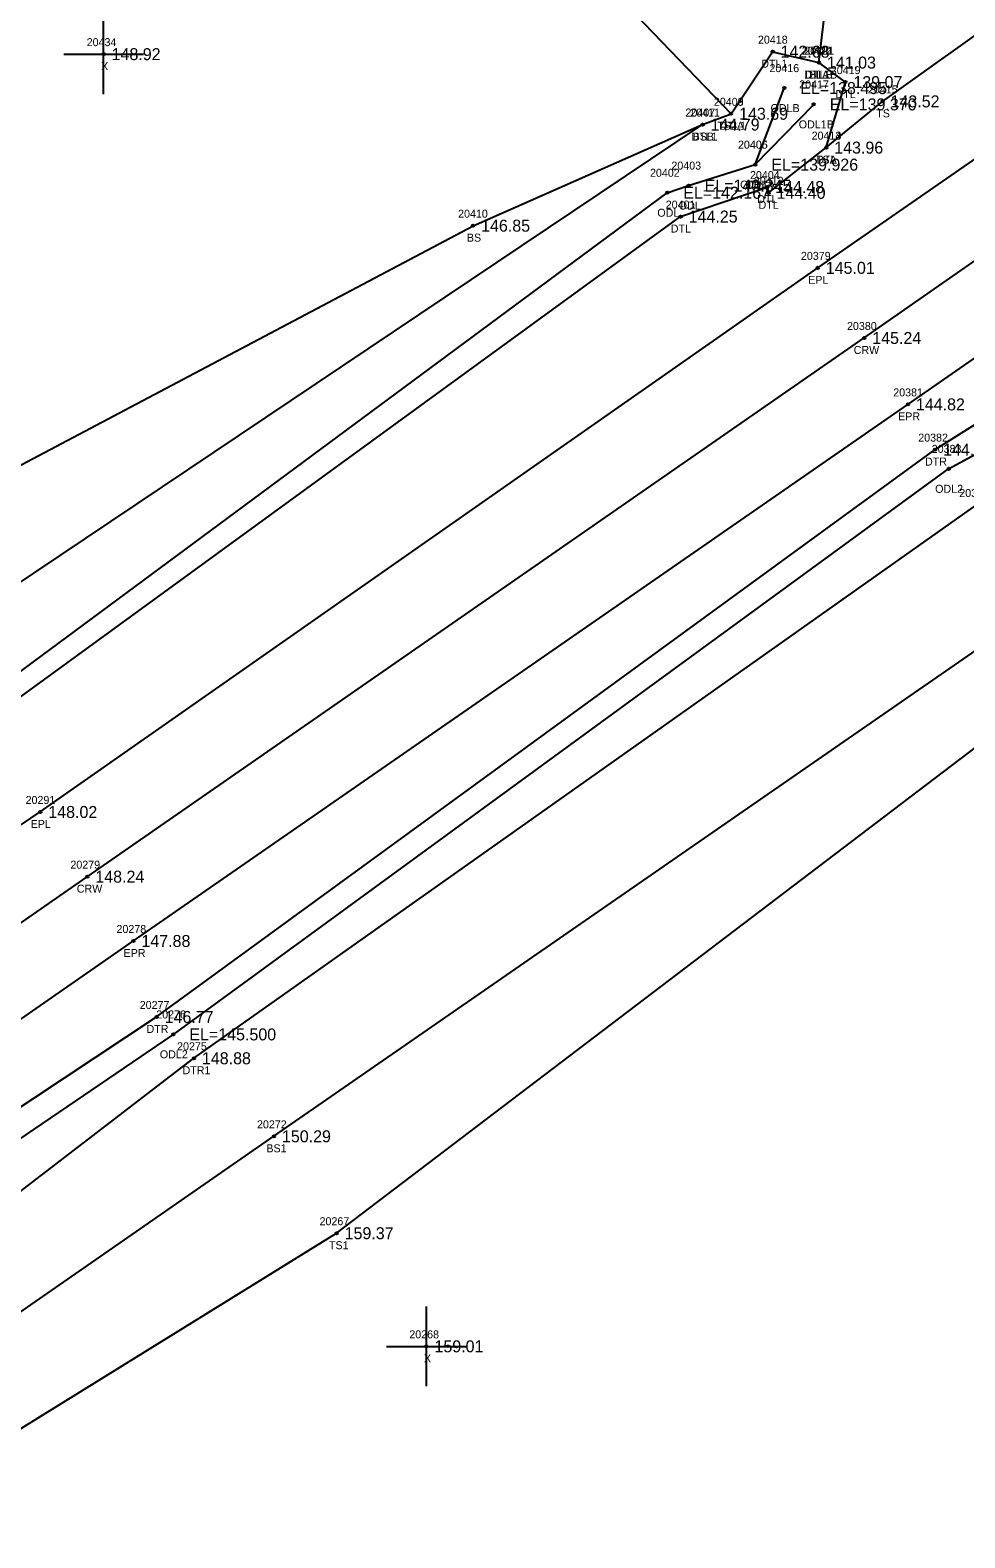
# Model space of a CAD drawing. Extents: x 2449605 to 2452431, y 1012876 to 1014922.
# Drawn here: x 2450635.2 to 2450752.2, y 1013571.4 to 1013760.1 of the extents above; entities that cross this region are included whole.
import ezdxf

# ---------------------------------------------------------------- set-up
doc = ezdxf.new("R2010")
doc.units = 0
for name, color, linetype in [('RD_DTM_BkLn1', 7, 'Continuous'), ('RD_DTM_BkLn2', 7, 'Continuous'), ('RD_DTM_BkLn_txCode', 7, 'Continuous'), ('RD_EX_H2O', 7, 'Continuous'), ('RD_EX_H2O_txCode', 7, 'Continuous'), ('RD_EX_Misc', 7, 'Continuous'), ('RD_EX_Misc_txCode', 7, 'Continuous'), ('RD_EX_Road', 7, 'Continuous'), ('RD_EX_Road_txCode', 7, 'Continuous'), ('RD_EX_TX_H2O_ELEV', 7, 'Continuous'), ('RD_EX_TX_Misc_ELEV', 7, 'Continuous'), ('RD_EX_TX_Road_ELEV', 7, 'Continuous'), ('RD_HC_Survey_ELEV', 7, 'Continuous'), ('RD_HC_Survey_txCode', 7, 'Continuous'), ('RD_SMD_Locator', 7, 'Continuous')]:
    doc.layers.add(name, color=color, linetype=linetype)

msp = doc.modelspace()

# ---------------------------------------------------------------- linework, layer by layer
at = {"layer": 'RD_DTM_BkLn1'}
msp.add_line((2450733.94, 1013756.08), (2450735.55, 1013769.66), dxfattribs=at)
msp.add_lwpolyline([(2449680.58, 1012985.87), (2449759.39, 1013040.31), (2449841.07, 1013097.15), (2449921.06, 1013152.87), (2450001.23, 1013208.89), (2450080.46, 1013264.17), (2450161.02, 1013320.22), (2450242.03, 1013376.29), (2450324.02, 1013432.88), (2450405.2, 1013489.3), (2450483.11, 1013543.86), (2450561.65, 1013598.14), (2450642.32, 1013654.18), (2450739.61, 1013721.61), (2450817.44, 1013775.86), (2450896.72, 1013831.42), (2450912.5, 1013842.34)], dxfattribs=at)
at = {"layer": 'RD_DTM_BkLn2'}
for points in [[(2450734.85, 1013745.44), (2450741.9, 1013751.23), (2450806.37, 1013797.26), (2450885.66, 1013846.42), (2450899.45, 1013853.56), (2450903.21, 1013856.03), (2450907.21, 1013856.3), (2450907.64, 1013854.05)], [(2450722.94, 1013749.68), (2450695.87, 1013777.83), (2450690.89, 1013781.55), (2450641.18, 1013772.81), (2450601.99, 1013777.82)], [(2450527.39, 1013753.89), (2450556.64, 1013730.22), (2450577.28, 1013715.46), (2450602.01, 1013688.84), (2450690.63, 1013735.67), (2450719.37, 1013748.33)], [(2450412.23, 1013445.13), (2450426.44, 1013458.74), (2450478.83, 1013491.33), (2450509.44, 1013509.8), (2450583.06, 1013564.41), (2450665.69, 1013621.68), (2450761.87, 1013688.24)], [(2450412.23, 1013445.13), (2450429.68, 1013454.01), (2450482, 1013483.09), (2450515.13, 1013504.99), (2450586.83, 1013555.92), (2450673.54, 1013609.55), (2450768.32, 1013681.57)]]:
    msp.add_lwpolyline(points, dxfattribs=at)
at = {"layer": 'RD_EX_H2O'}
msp.add_line((2450725.97, 1013743.31), (2450733.29, 1013750.85), dxfattribs=at)
for points in [[(2450611.14, 1013666.87), (2450616.31, 1013679.25), (2450719.37, 1013748.33), (2450722.94, 1013749.68), (2450728.13, 1013757.45), (2450733.94, 1013756.08)], [(2450611.14, 1013666.87), (2450613.78, 1013662.06), (2450716.62, 1013736.81), (2450727.45, 1013740.5), (2450727.63, 1013739.78), (2450734.85, 1013745.44), (2450737.25, 1013753.64), (2450733.94, 1013756.08)], [(2450614.33, 1013665.39), (2450714.94, 1013739.79), (2450717.62, 1013740.69), (2450725.97, 1013743.31), (2450729.59, 1013752.89)], [(2450167.46, 1013291.72), (2450167.1, 1013295.75), (2450175.19, 1013302.21), (2450253.51, 1013357.72), (2450334.87, 1013415.7), (2450415.19, 1013473.64), (2450493.27, 1013528.65), (2450573.99, 1013585.66), (2450651, 1013636.62), (2450748.48, 1013707.64), (2450786.48, 1013731.51)], [(2450167.46, 1013291.72), (2450171.71, 1013290.19), (2450180.8, 1013296.66), (2450259.89, 1013349.14), (2450344.33, 1013402.02), (2450412.23, 1013445.13), (2450424.15, 1013461.12), (2450474.5, 1013497.19), (2450500.92, 1013517.59), (2450581.65, 1013574.66), (2450655.67, 1013631.45), (2450753.63, 1013700.7), (2450792.21, 1013722.47), (2450790.93, 1013725.57), (2450786.48, 1013731.51)], [(2450169.6, 1013293.28), (2450177.31, 1013300.27), (2450255.34, 1013355.6), (2450337.16, 1013412.65), (2450417.79, 1013470.31), (2450495.24, 1013525.07), (2450576.17, 1013582.13), (2450653.09, 1013634.44), (2450750.18, 1013705.23), (2450772.07, 1013717.13), (2450787.49, 1013726.73)]]:
    msp.add_lwpolyline(points, dxfattribs=at)
at = {"layer": 'RD_EX_Misc'}
for p, q in [((2450644.36, 1013752.14), (2450644.36, 1013762.14)), ((2450639.36, 1013757.14), (2450649.36, 1013757.14)), ((2450684.79, 1013590.39), (2450684.79, 1013600.39)), ((2450679.79, 1013595.39), (2450689.79, 1013595.39))]:
    msp.add_line(p, q, dxfattribs=at)
at = {"layer": 'RD_EX_Road'}
for points in [[(2449674.89, 1012994.69), (2449752.35, 1013048.28), (2449834.92, 1013105.96), (2449914.72, 1013161.11), (2449995.66, 1013217.59), (2450075.29, 1013272.9), (2450081.34, 1013277.24), (2450093.41, 1013285.64), (2450155.49, 1013328.69), (2450236.05, 1013384.7), (2450317.88, 1013441.24), (2450398.87, 1013497.28), (2450477.09, 1013551.76), (2450555.6, 1013606.73), (2450600.18, 1013637.7), (2450618.08, 1013649.65), (2450627.95, 1013656.57), (2450636.43, 1013662.28), (2450733.79, 1013730.39), (2450811.43, 1013784.18), (2450891.39, 1013839.9), (2450907.04, 1013850.14)], [(2449685.94, 1012977.62), (2449764.81, 1013032.3), (2449846, 1013088.39), (2449925.85, 1013144.07), (2450006.8, 1013200.56), (2450086.45, 1013256.14), (2450125.67, 1013283.43), (2450163.55, 1013309.93), (2450166.36, 1013312.09), (2450247.44, 1013367.98), (2450329.19, 1013424.41), (2450410.32, 1013481.09), (2450488.38, 1013535.38), (2450567.5, 1013590.14), (2450648.09, 1013646.13), (2450745.08, 1013713.3), (2450823, 1013767.39), (2450902.19, 1013823.2), (2450918.14, 1013833.95)]]:
    msp.add_lwpolyline(points, dxfattribs=at)
at = {"layer": 'RD_SMD_Locator'}
for centre in [(2450644.36, 1013757.14), (2450728.13, 1013757.45), (2450733.94, 1013756.08), (2450733.94, 1013756.08), (2450733.94, 1013756.08), (2450729.59, 1013752.89), (2450737.25, 1013753.64), (2450733.29, 1013750.85), (2450741.9, 1013751.23), (2450719.37, 1013748.33), (2450719.37, 1013748.33), (2450722.94, 1013749.68), (2450722.94, 1013749.68), (2450734.85, 1013745.44), (2450734.85, 1013745.44), (2450725.97, 1013743.31), (2450725.97, 1013743.31), (2450717.62, 1013740.69), (2450714.94, 1013739.79), (2450727.45, 1013740.5), (2450727.63, 1013739.78), (2450690.63, 1013735.67), (2450716.62, 1013736.81), (2450733.79, 1013730.39), (2450739.61, 1013721.61), (2450745.08, 1013713.3), (2450748.48, 1013707.64), (2450750.18, 1013705.23), (2450636.43, 1013662.28), (2450642.32, 1013654.18), (2450648.09, 1013646.13), (2450651, 1013636.62), (2450653.09, 1013634.44), (2450655.67, 1013631.45), (2450665.69, 1013621.68), (2450673.54, 1013609.55), (2450684.79, 1013595.39)]:
    msp.add_circle(centre, 0.15, dxfattribs=at)

# ---------------------------------------------------------------- texts
at = {"layer": 'RD_DTM_BkLn_txCode'}
for s, p in [('20422', (2450731.82, 1013757.08)), ('BLA', (2450732.7, 1013754.08)), ('20415', (2450740.07, 1013752.23)), ('20411', (2450717.82, 1013749.33)), ('20409', (2450720.78, 1013750.68)), ('TS', (2450741.11, 1013749.23)), ('TS2A', (2450721.21, 1013747.68)), ('BSB', (2450718.12, 1013746.33)), ('20414', (2450733.02, 1013746.44)), ('TSA', (2450733.57, 1013743.44)), ('20410', (2450688.75, 1013736.67)), ('BS', (2450689.85, 1013733.67)), ('20272', (2450663.57, 1013622.68)), ('BS1', (2450664.74, 1013619.68)), ('20267', (2450671.4, 1013610.55)), ('TS1', (2450672.58, 1013607.55))]:
    msp.add_text(s, height=1, dxfattribs=at).set_placement(p)
at = {"layer": 'RD_EX_H2O_txCode'}
for s, p in [('20418', (2450726.3, 1013758.45)), ('20420', (2450731.78, 1013757.08)), ('20421', (2450732.11, 1013757.08)), ('DTL1', (2450726.72, 1013755.45)), ('20416', (2450727.74, 1013754.89)), ('DTL1B', (2450732.06, 1013754.08)), ('DTLB', (2450732.22, 1013754.08)), ('20419', (2450735.42, 1013754.64)), ('20417', (2450731.46, 1013752.85)), ('DTL', (2450736.01, 1013751.64)), ('20407', (2450717.22, 1013749.33)), ('20408', (2450720.78, 1013750.68)), ('ODLB', (2450727.88, 1013749.89)), ('DTL1', (2450721.53, 1013747.68)), ('ODL1B', (2450731.41, 1013747.85)), ('DTL1', (2450717.96, 1013746.33)), ('20413', (2450733.02, 1013746.44)), ('20406', (2450723.79, 1013745.31)), ('20405', (2450723.81, 1013745.31)), ('20402', (2450712.78, 1013741.79)), ('20403', (2450715.46, 1013742.69)), ('DTL', (2450733.61, 1013743.44)), ('ODL1A', (2450724.07, 1013740.31)), ('ODL', (2450724.72, 1013740.31)), ('20404', (2450725.3, 1013741.5)), ('20412', (2450725.79, 1013740.78)), ('DTL', (2450726.21, 1013738.5)), ('ODL', (2450713.7, 1013736.79)), ('20401', (2450714.75, 1013737.81)), ('ODL', (2450716.38, 1013737.69)), ('DTL', (2450726.38, 1013737.78)), ('DTL', (2450715.38, 1013734.81)), ('20382', (2450746.37, 1013708.64)), ('20383', (2450748.06, 1013707.23)), ('DTR', (2450747.22, 1013705.64)), ('ODL2', (2450748.49, 1013702.23)), ('20384', (2450751.51, 1013701.7)), ('20277', (2450648.88, 1013637.62)), ('20276', (2450650.95, 1013636.44)), ('DTR', (2450649.73, 1013634.62)), ('20275', (2450653.56, 1013632.45)), ('ODL2', (2450651.4, 1013631.44)), ('DTR1', (2450654.24, 1013629.45))]:
    msp.add_text(s, height=1, dxfattribs=at).set_placement(p)
at = {"layer": 'RD_EX_Misc_txCode'}
for s, p in [('20434', (2450642.24, 1013758.14)), ('X', (2450644.04, 1013755.14)), ('20268', (2450682.64, 1013596.39)), ('X', (2450684.47, 1013593.39))]:
    msp.add_text(s, height=1, dxfattribs=at).set_placement(p)
at = {"layer": 'RD_EX_Road_txCode'}
for s, p in [('20379', (2450731.68, 1013731.39)), ('EPL', (2450732.59, 1013728.39)), ('20381', (2450743.24, 1013714.3)), ('EPR', (2450743.85, 1013711.3)), ('20291', (2450634.59, 1013663.28)), ('EPL', (2450635.22, 1013660.28)), ('20278', (2450645.97, 1013647.13)), ('EPR', (2450646.86, 1013644.13))]:
    msp.add_text(s, height=1, dxfattribs=at).set_placement(p)
at = {"layer": 'RD_EX_TX_H2O_ELEV'}
for s, p in [('142.68', (2450729.13, 1013756.7)), ('141.03', (2450734.94, 1013755.33)), ('141.03', (2450734.94, 1013755.33)), ('139.07', (2450738.25, 1013752.89)), ('EL=138.495', (2450731.59, 1013752.14)), ('143.69', (2450723.94, 1013748.93)), ('EL=139.370', (2450735.29, 1013750.1)), ('144.79', (2450720.37, 1013747.58)), ('143.96', (2450735.85, 1013744.69)), ('EL=139.926', (2450727.97, 1013742.56)), ('EL=139.926', (2450727.97, 1013742.56)), ('EL=140.345', (2450719.62, 1013739.94)), ('144.48', (2450728.45, 1013739.75)), ('EL=142.167', (2450716.94, 1013739.04)), ('144.40', (2450728.63, 1013739.03)), ('144.25', (2450717.62, 1013736.06)), ('144.00', (2450749.48, 1013706.89)), ('146.77', (2450652, 1013635.87)), ('EL=145.500', (2450655.09, 1013633.69)), ('148.88', (2450656.67, 1013630.7))]:
    msp.add_text(s, height=1.5, dxfattribs=at).set_placement(p)
at = {"layer": 'RD_EX_TX_Misc_ELEV'}
for s, p in [('148.92', (2450645.36, 1013756.39)), ('141.03', (2450734.94, 1013755.33)), ('143.69', (2450723.94, 1013748.93)), ('143.52', (2450742.9, 1013750.48)), ('144.79', (2450720.37, 1013747.58)), ('143.96', (2450735.85, 1013744.69)), ('146.85', (2450691.63, 1013734.92)), ('150.29', (2450666.69, 1013620.93)), ('159.37', (2450674.54, 1013608.8)), ('159.01', (2450685.79, 1013594.64))]:
    msp.add_text(s, height=1.5, dxfattribs=at).set_placement(p)
at = {"layer": 'RD_EX_TX_Road_ELEV'}
for s, p in [('145.01', (2450734.79, 1013729.64)), ('144.82', (2450746.08, 1013712.55)), ('148.02', (2450637.43, 1013661.53)), ('147.88', (2450649.09, 1013645.38))]:
    msp.add_text(s, height=1.5, dxfattribs=at).set_placement(p)
at = {"layer": 'RD_HC_Survey_ELEV'}
for s, p in [('145.24', (2450740.61, 1013720.86)), ('148.24', (2450643.32, 1013653.43))]:
    msp.add_text(s, height=1.5, dxfattribs=at).set_placement(p)
at = {"layer": 'RD_HC_Survey_txCode'}
for s, p in [('20380', (2450737.45, 1013722.61)), ('CRW', (2450738.29, 1013719.61)), ('20279', (2450640.2, 1013655.18)), ('CRW', (2450641, 1013652.18))]:
    msp.add_text(s, height=1, dxfattribs=at).set_placement(p)

doc.saveas('drawing.dxf')
